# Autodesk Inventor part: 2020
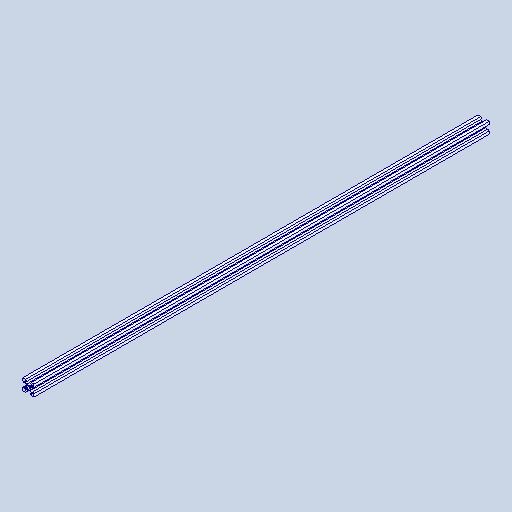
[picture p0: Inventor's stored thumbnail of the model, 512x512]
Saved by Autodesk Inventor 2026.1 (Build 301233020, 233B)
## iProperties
Created: 2024-09
Part Number: 2020
Material: Alluminio 6061
Document SubType Name: Modeling
Designer: hp
Density: 2.7 g/cm^3
Appearance: Default
Author: hp
Revision Number: ANY
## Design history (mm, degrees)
node "Solido1"
sketch "Sketch3"
  geometry: 2 further points
hole "Hole3" sketch "Sketch3" at (32.222, -3.027), (16.972, -3.027) diameter "d14" = 4.5; stored, may be unused: countersink angle "d18" = 90 deg, drill point angle "d20" = 0 deg; dims "d15" = 6, "d16" = 4, "d17" = 2, "d19" = 8
sketch "Sketch6"
  geometry: 2 further points
hole "Hole6" sketch "Sketch6" at (797, 3.053), (810, 3.053) diameter "d35" = 4.5; stored, may be unused: countersink angle "d39" = 90 deg, drill point angle "d41" = 0 deg; dims "d36" = 6, "d37" = 4, "d38" = 2, "d40" = 8
sketch "Sketch7"
  geometry: 2 further points
hole "Hole7" sketch "Sketch7" at (93.5, -3.027), (109.5, -3.027) diameter "d42" = 3.4; stored, may be unused: countersink angle "d46" = 90 deg, drill point angle "d48" = 0 deg; dims "d43" = 6, "d44" = 4, "d45" = 2, "d47" = 8
sketch "Sketch9"
  geometry: 2 further points
hole "Hole9" sketch "Sketch9" at (692.5, -3.027), (708.5, -3.027) diameter "d56" = 3.4; stored, may be unused: countersink angle "d60" = 90 deg, drill point angle "d62" = 0 deg; dims "d57" = 6, "d58" = 4, "d59" = 2, "d61" = 8
body "Solid1"
